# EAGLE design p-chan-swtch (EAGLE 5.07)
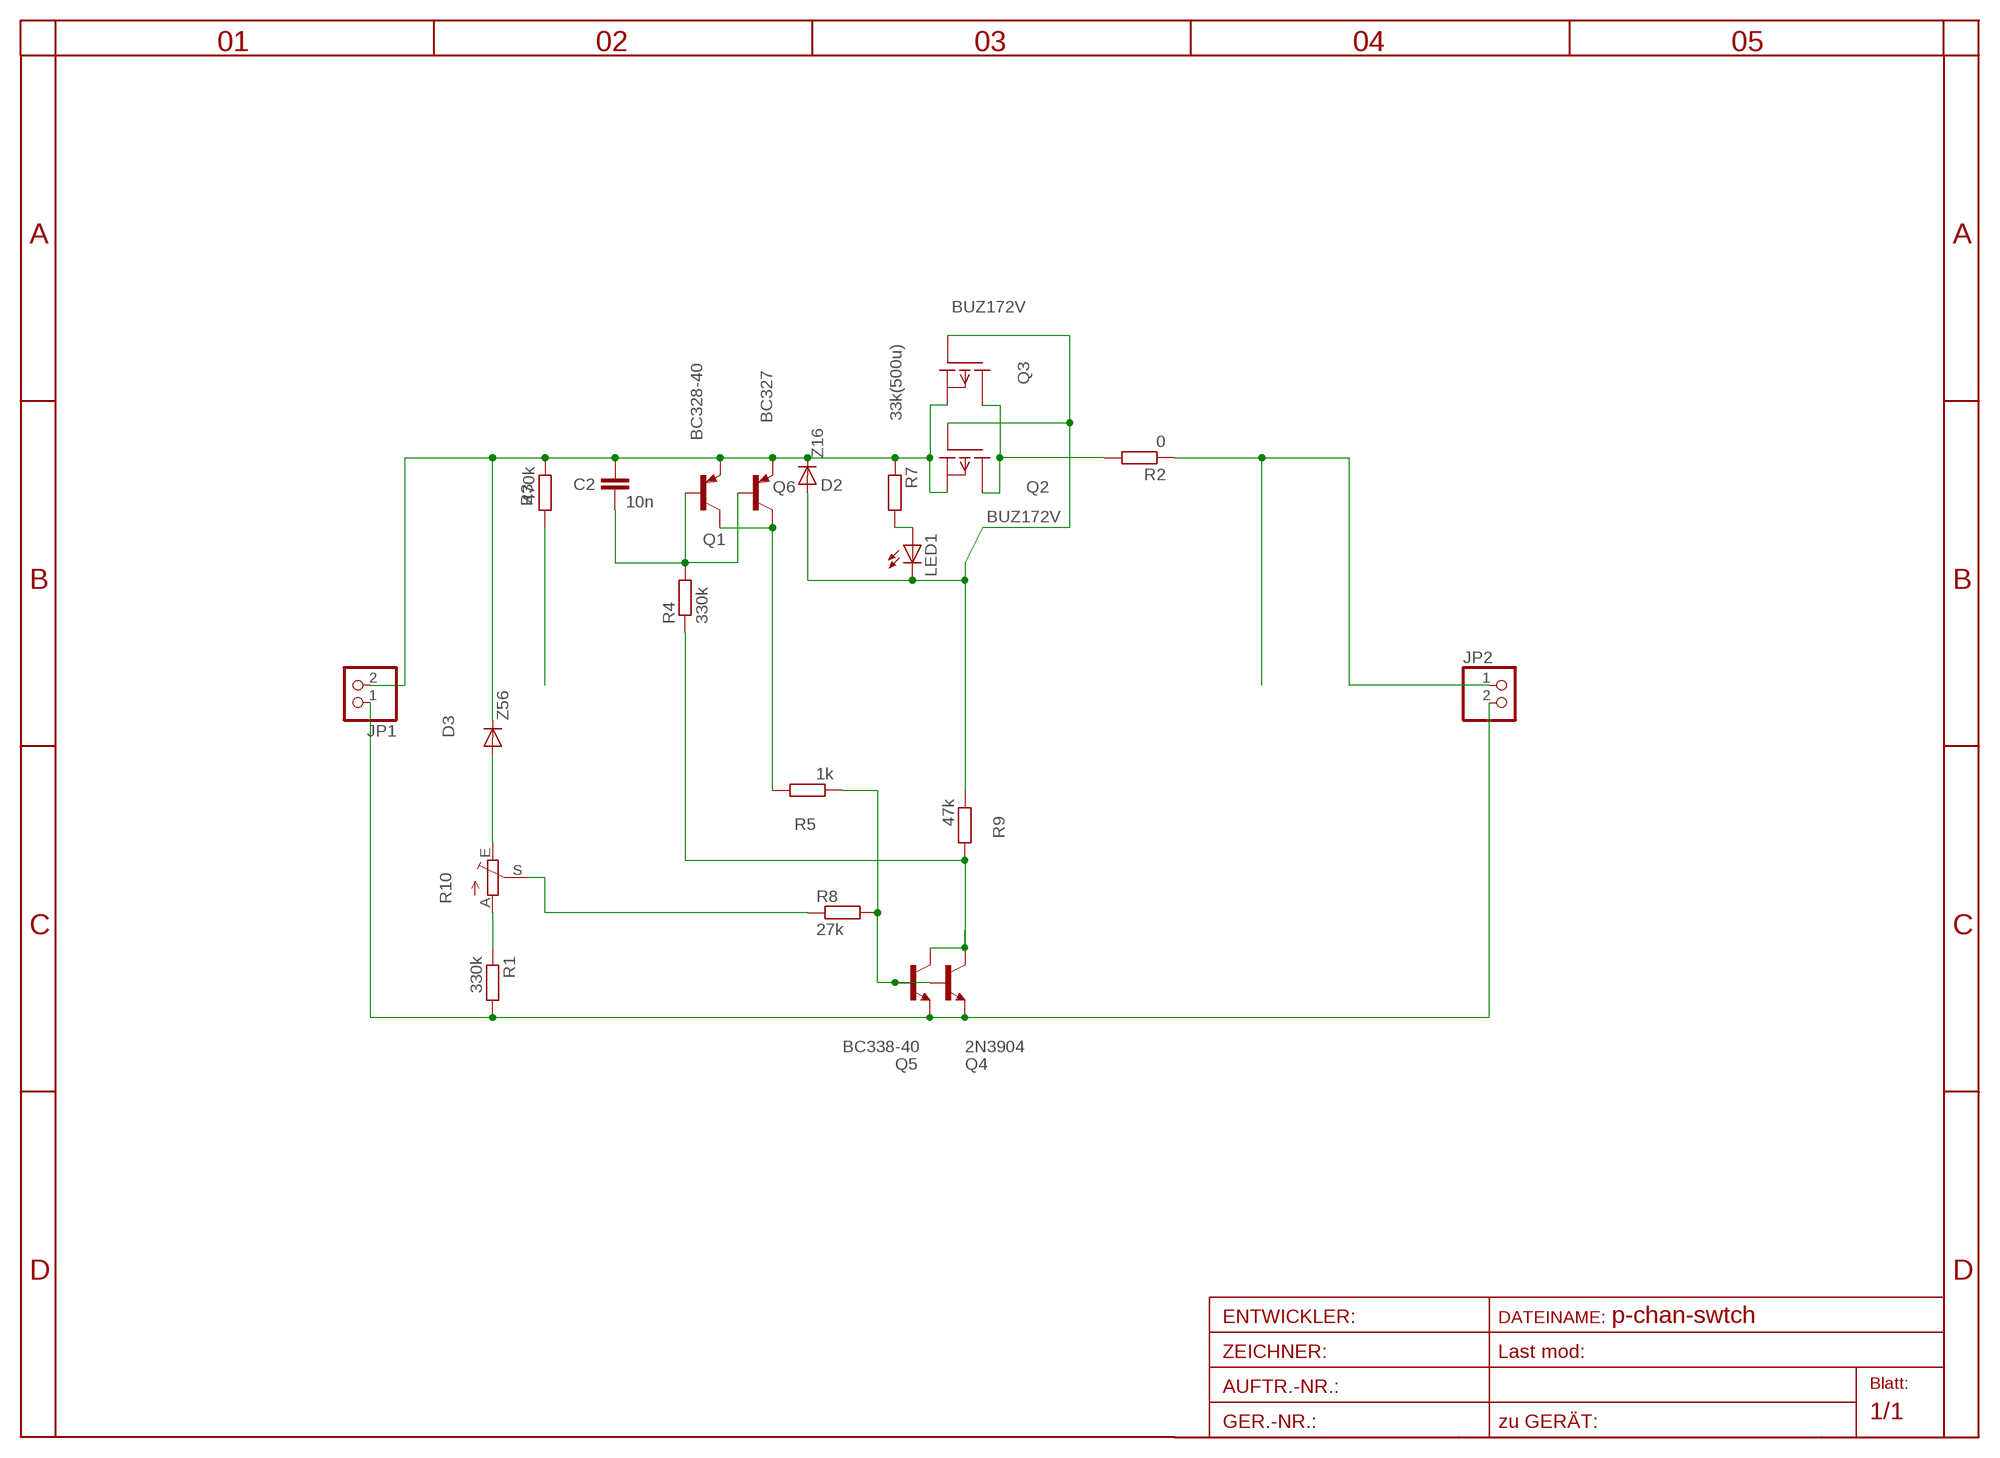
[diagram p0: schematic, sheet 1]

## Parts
C2  10n  C-EU025-024X044  [C025-024X044]
D2  Z16  DIODE-D-7.5  [D-7.5]
D3  Z56  DIODE-MINIMELF  [MINIMELF]
JP1  PINHD-1X2  [1X02]
JP2  PINHD-1X2  [1X02]
LED1  LED3MM  [LED3MM]
Q1  BC328-40  [TO92-EBC]
Q2  BUZ172V  [TO220V]
Q3  BUZ172V  [TO220V]
Q4  2N3904  [TO92]
Q5  BC338-40  [TO92-EBC]
Q6  BC327  [TO92]
R1  330k  R-EU_0204/7  [0204/7]
R2  0  R-EU_0204/5  [0204/5]
R3  470k  R-EU_0204/5  [0204/5]
R4  330k  R-EU_0204/7  [0204/7]
R5  1k  R-EU_0207/40  [0207/40]
R7  33k(500u)  R-EU_0204/7  [0204/7]
R8  27k  R-EU_0204/7  [0204/7]
R9  47k  R-EU_0204/5  [0204/5]
R10  TRIM_EU-EVND_H  [EVND8AA]

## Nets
B-Q1: C2.2 Q1.B Q6.2(B) R4.2
C-Q1: Q1.C Q6.3(C) R5.2
C-Q4: Q4.1(C) Q5.C R4.1 R9.2
GATE: D2.A LED1.K(C) Q2.1(G) Q3.1(G) R9.1
N$1: R8.1 R10.S
N$2: R1.1 R10.A
N$3: LED1.A R7.2
N$4: D3.A R10.E
N$6: R3.2
N$9: Q2.2(D) Q3.2(D) R2.2
N$13: Q4.2(B) Q5.B R5.1 R8.2
V+IN: C2.1 D2.C D3.C JP1.2 Q1.E Q2.3(S) Q3.3(S) Q6.1(E) R3.1 R7.1
V+OUT: JP2.1 R2.1
V-: JP1.1 JP2.2 Q4.3(E) Q5.E R1.2

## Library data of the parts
C2 = rcl-2:C-EU: CAPACITOR, European symbol
D2 D3 = diode-1:DIODE-: DIODE
JP1 JP2 = pinhead:PINHD-1X2: PIN HEADER
LED1 = led:LED: LED
Q1 = transistor-pnp:BC328*: PNP Transistror
Q2 Q3 = transistor-fet:BUZ172: P-Channel Enhancement MOSFET -100V; -5A; 0,8Ohm
Q4 = transistor-npn:2N3904: NPN Transistor
Q5 = transistor-npn:BC338*: NPN Transistor
Q6 = transistor-pnp:BC327: PNP Transistor
R1-R5 R7-R9 = rcl-2:R-EU_: RESISTOR, European symbol
R10 = pot:TRIM_EU-: POTENTIOMETER

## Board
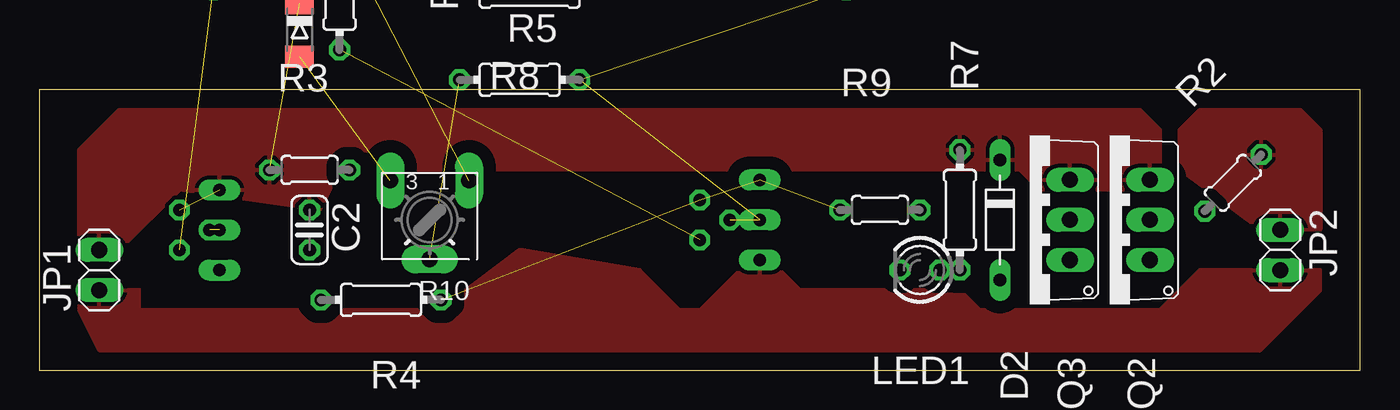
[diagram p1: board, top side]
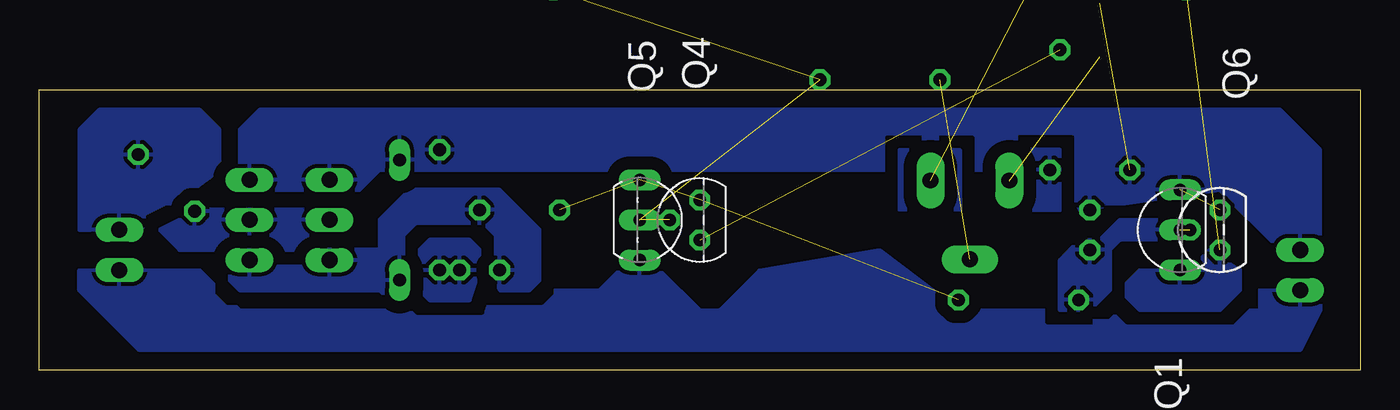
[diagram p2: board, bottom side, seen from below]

Size 83.82 x 17.78 mm. Coordinates in mm from the lower left corner, seen from the top.
Outline: 0,0 83.82,0 83.82,17.78 0,17.78 0,0
Copper layers (1*16): Top 0.035mm / dielectric 1.5mm / Bottom 0.035mm
Design rules "default": minimum track width 10mil, minimum drill 24mil, track to track 8mil, track to pad 8mil, pad to pad 8mil, via to via 8mil, smd to smd 8mil, copper to edge 40mil, drill to drill 8mil, minimum pad ring 10mil, minimum via ring 8mil, stop-mask expansion 4mil, vias tented up to drill 0mil, thermal gap 10mil

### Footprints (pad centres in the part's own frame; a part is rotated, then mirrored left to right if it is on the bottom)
C025-024X044 = drill 0.813 octagon: 1 -1.27,0; 2 1.27,0
D-7.5 = drill 0.813 long: A 3.81,0; C -3.81,0
MINIMELF = smd 1.4 x 1.8: A 1.7,0; C -1.7,0
1X02 = drill 1.016 long: 1 -1.27,0; 2 1.27,0
LED3MM = drill 0.813 octagon: A -1.27,0; K 1.27,0
TO92-EBC = drill 0.813 long: B 0,-1.27; C -2.54,-1.27; E 2.54,-1.27
TO220V = drill 1.016 long: 1 -2.54,-2.54; 2 0,-2.54; 3 2.54,-2.54
TO92 = drill 0.813 octagon: 1 1.27,0; 2 0,1.905; 3 -1.27,0
0204/7 = drill 0.813 octagon: 1 -3.81,0; 2 3.81,0
0204/5 = drill 0.813 octagon: 1 -2.54,0; 2 2.54,0
0207/40 = drill 0.813 octagon: 1 -20.08,0; 2 20.08,0
EVND8AA = drill 1 pad 1.778 long: A -2.5,-2.5; E 2.5,-2.5; S 0,2.5

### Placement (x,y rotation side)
C2  17.14,8.89 270 top
D2  60.96,9.53 270 top
D3  16.51,21.59 270 top
JP1  3.81,6.35 90 top
JP2  78.74,7.62 270 top
LED1  55.88,6.35 180 top
Q1  12.7,8.89 90 bottom
Q2  67.94,9.53 90 top
Q3  62.87,9.53 90 top
Q4  41.91,9.53 90 bottom
Q5  44.45,9.53 270 bottom
Q6  8.89,8.89 90 bottom
R1  19.05,24.13 270 top
R2  75.75,11.88 225 top
R3  17.14,12.7 0 top
R4  21.68,4.45 180 top
R5  not placed on the board
R7  58.42,10.16 270 top
R8  30.48,18.41 0 top
R9  53.34,10.16 180 top
R10  24.77,9.53 180 top

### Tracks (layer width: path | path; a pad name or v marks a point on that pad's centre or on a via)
B-Q1  (1 unrouted)
  pour Bottom (isolate 0.813, rank 2): 19.05,3.81 19.05,6.99 17.78,8.26 16.51,8.26 15.24,9.53 12.06,9.53 12.06,8.26 15.24,8.26 15.88,7.62 15.88,5.08 17.14,3.81
C-Q1  (1 unrouted)
  pour Bottom (isolate 0.813, rank 4): 7.62,6.35 7.62,5.08 8.89,3.81 13.97,3.81 15.24,5.08 13.97,6.35 10.79,6.35 9.53,7.62
C-Q4  (3 unrouted)
GATE
  pour Bottom (isolate 0.813, rank 2): 54.61,5.08 52.7,5.08 52.07,5.71 52.07,8.89 54.61,11.43 60.33,11.43 62.23,9.53 62.23,7.62 71.12,7.62 71.75,6.99 71.75,5.71 71.12,5.08 62.23,5.08 61.59,4.45 59.69,6.35 59.69,8.26 55.88,8.26
N$1  (1 unrouted)
N$2  (1 unrouted)
N$3
  pour Bottom (isolate 0.813): 55.88,6.35 55.88,7.62 56.52,8.26 59.05,8.26 59.69,7.62 59.69,5.08 59.05,4.45 56.52,4.45
N$4  (1 unrouted)
N$6
  pour Bottom (isolate 0.813, rank 3): 19.05,13.97 24.13,13.97 24.13,11.43 22.86,10.16 19.05,10.16
N$9
  pour Bottom (isolate 0.813): 66.04,10.16 73.66,10.16 76.2,8.89 74.93,7.62 67.31,7.62 66.04,8.89
N$13  (3 unrouted)
V+IN  (2 unrouted)
  pour Bottom (isolate 0.813, rank 5): 2.54,7.62 2.54,13.97 5.08,16.51 69.85,16.51 71.12,15.24 71.12,12.7 69.85,11.43 63.5,11.43 62.23,12.7 19.05,12.7 17.78,10.16 8.89,11.43 5.08,7.62
  pour Top (isolate 0.813, rank 5): 2.54,7.62 2.54,13.97 5.08,16.51 69.85,16.51 71.12,15.24 71.12,12.7 69.85,11.43 63.5,11.43 62.23,12.7 19.05,12.7 17.78,10.16 8.89,11.43 5.08,7.62
V+OUT
  pour Bottom (isolate 0.813, rank 5): 72.39,12.7 72.39,15.24 73.66,16.51 80.01,16.51 81.28,15.24 81.28,8.89 77.47,8.89
  pour Bottom (isolate 0.813, rank 3): 25.4,13.97 25.4,10.16 29.21,10.16 29.21,13.97
  pour Top (isolate 0.813, rank 5): 72.39,12.7 72.39,15.24 73.66,16.51 80.01,16.51 81.28,15.24 81.28,8.89 77.47,8.89
V-  (1 unrouted)
  pour Bottom (isolate 0.813, rank 5): 2.54,3.81 3.81,1.27 77.47,1.27 81.28,5.08 81.28,6.35 73.66,6.35 71.12,3.81 59.69,3.81 58.42,5.08 48.26,5.08 46.99,6.35 44.45,6.35 41.91,3.81 40.64,3.81 38.1,6.35 30.48,7.62 25.4,3.81 6.35,3.81 6.35,5.08 2.54,5.08
  pour Top (isolate 0.813, rank 5): 2.54,3.81 3.81,1.27 77.47,1.27 81.28,5.08 81.28,6.35 73.66,6.35 71.12,3.81 59.69,3.81 58.42,5.08 48.26,5.08 46.99,6.35 44.45,6.35 41.91,3.81 40.64,3.81 38.1,6.35 30.48,7.62 25.4,3.81 6.35,3.81 6.35,5.08 2.54,5.08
